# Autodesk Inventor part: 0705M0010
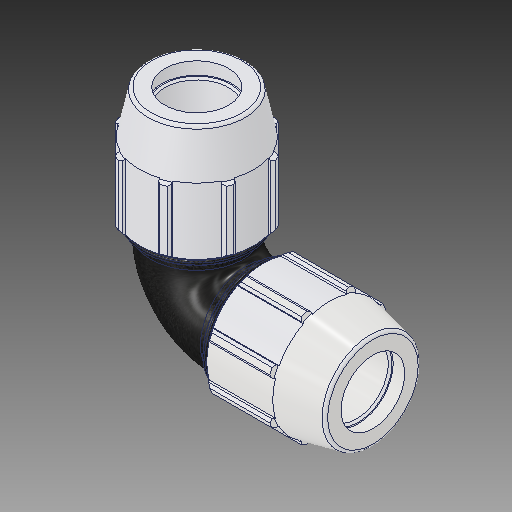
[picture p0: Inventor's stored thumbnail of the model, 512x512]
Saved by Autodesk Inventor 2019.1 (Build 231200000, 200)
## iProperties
Created: 2017-02
Part Number: 0705M0010
Material: PVC-Piping
Description: PLASSON 90° ELBOW 1'' - 1''
Document SubType Name: Modeling
Designer: KIM
Mass: 92.6774 g
Surface Area: 199.44 cm^2
Volume: 66.1981 cm^3
Density: 1.4 g/cm^3
Appearance: PTFE
Author: KIM
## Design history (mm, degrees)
derived "0705M0.ipt"
feature "Solid1::0705M0.ipt"
tag "TaggingFeature1"
body "Solid1"
other parameters: "d2" = 33.3, "d4" = 7.66233, "d5" = 22.987, "d7" = 64.008, "d9" = 13.13543, "d11" = 2.2987, "d13" = 120 deg, "d14" = 49.95, "d15" = 12 deg, "d16" = 55.68696, "d18" = 1.665, "d19" = 35 deg, "d20" = 17.5 deg, "d21" = 59.52744, "d23" = 0, "d25" = 360 deg, "d27" = 1.28016, "d33" = 0.666, "d42" = 34.02076, "d43" = 1.92024, "d46" = 0.999, "d51" = 91.948, "d59" = 90 deg, "d63" = 66.04, "d64" = 29.97, "d67" = 48.006, "d68" = 2.2987, "d70" = 90 deg, "d_" = 33.3, "E_" = 64.008, "A_" = 91.948, "l_" = 66.04
